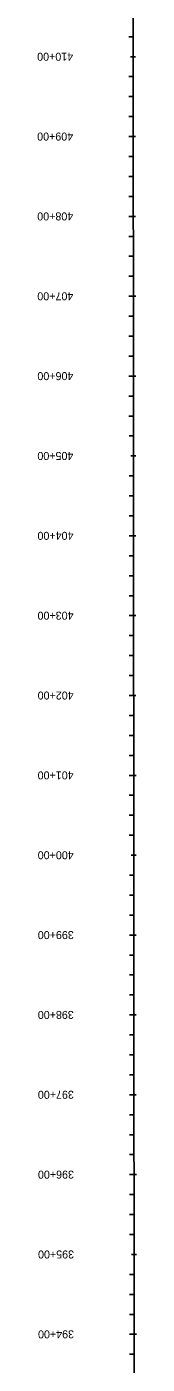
# Model space of a CAD drawing. Extents: x 23417911 to 23421158, y 6737892 to 6791804.
# Drawn here: x 23420714 to 23420838, y 6764860 to 6766535 of the extents above; entities that cross this region are included whole.
import ezdxf

# ---------------------------------------------------------------- set-up
doc = ezdxf.new("R2010")
doc.units = 0
for name, color, linetype in [('Alignment', 7, 'Continuous'), ('TextAlignmentLrg', 7, 'Continuous'), ('TextAlignmentSml', 7, 'Continuous')]:
    doc.layers.add(name, color=color, linetype=linetype)

msp = doc.modelspace()

# ---------------------------------------------------------------- linework, layer by layer
at = {"layer": 'Alignment'}
msp.add_line((23420834.6, 6764732), (23420829.5, 6771769.1), dxfattribs=at)
msp.add_line((23420834.6, 6764732), (23420829.5, 6771769.1), dxfattribs=at)
at = {"layer": 'TextAlignmentLrg'}
for p, q in [((23420830.2, 6766497.6), (23420836.3, 6766497.6)), ((23420833.4, 6766397.6), (23420827.9, 6766397.6)), ((23420833.4, 6766297.6), (23420828, 6766297.6)), ((23420833.5, 6766197.6), (23420828, 6766197.6)), ((23420833.6, 6766097.6), (23420828.1, 6766097.6)), ((23420830.6, 6765997.6), (23420836.7, 6765997.6)), ((23420833.7, 6765897.6), (23420828.3, 6765897.6)), ((23420833.8, 6765797.6), (23420828.3, 6765797.6)), ((23420833.9, 6765697.6), (23420828.4, 6765697.6)), ((23420833.9, 6765597.6), (23420828.5, 6765597.6)), ((23420830.9, 6765497.6), (23420837.1, 6765497.6)), ((23420834.1, 6765397.6), (23420828.6, 6765397.6)), ((23420834.2, 6765297.6), (23420828.7, 6765297.6)), ((23420834.2, 6765197.6), (23420828.8, 6765197.6)), ((23420834.3, 6765097.6), (23420828.8, 6765097.6)), ((23420831.3, 6764997.6), (23420837.4, 6764997.6)), ((23420834.4, 6764897.6), (23420829, 6764897.6))]:
    msp.add_line(p, q, dxfattribs=at)
at = {"layer": 'TextAlignmentSml'}
for p, q in [((23420833.3, 6766522.6), (23420827.8, 6766522.6)), ((23420830.2, 6766497.6), (23420836.3, 6766497.6)), ((23420833.3, 6766472.6), (23420827.8, 6766472.6)), ((23420833.3, 6766447.6), (23420827.9, 6766447.6)), ((23420833.3, 6766422.6), (23420827.9, 6766422.6)), ((23420830.3, 6766397.6), (23420836.4, 6766397.6)), ((23420833.4, 6766372.6), (23420827.9, 6766372.6)), ((23420833.4, 6766347.6), (23420827.9, 6766347.6)), ((23420833.4, 6766322.6), (23420827.9, 6766322.6)), ((23420830.4, 6766297.6), (23420836.5, 6766297.6)), ((23420833.4, 6766272.6), (23420828, 6766272.6)), ((23420833.5, 6766247.6), (23420828, 6766247.6)), ((23420833.5, 6766222.6), (23420828, 6766222.6)), ((23420830.4, 6766197.6), (23420836.6, 6766197.6)), ((23420833.5, 6766172.6), (23420828.1, 6766172.6)), ((23420833.5, 6766147.6), (23420828.1, 6766147.6)), ((23420833.6, 6766122.6), (23420828.1, 6766122.6)), ((23420830.5, 6766097.6), (23420836.6, 6766097.6)), ((23420833.6, 6766072.6), (23420828.1, 6766072.6)), ((23420833.6, 6766047.6), (23420828.1, 6766047.6)), ((23420833.6, 6766022.6), (23420828.2, 6766022.6)), ((23420830.6, 6765997.6), (23420836.7, 6765997.6)), ((23420833.7, 6765972.6), (23420828.2, 6765972.6)), ((23420833.7, 6765947.6), (23420828.2, 6765947.6)), ((23420833.7, 6765922.6), (23420828.2, 6765922.6)), ((23420830.7, 6765897.6), (23420836.8, 6765897.6)), ((23420833.7, 6765872.6), (23420828.3, 6765872.6)), ((23420833.8, 6765847.6), (23420828.3, 6765847.6)), ((23420833.8, 6765822.6), (23420828.3, 6765822.6)), ((23420830.7, 6765797.6), (23420836.8, 6765797.6)), ((23420833.8, 6765772.6), (23420828.3, 6765772.6)), ((23420833.8, 6765747.6), (23420828.4, 6765747.6)), ((23420833.8, 6765722.6), (23420828.4, 6765722.6)), ((23420830.8, 6765697.6), (23420836.9, 6765697.6)), ((23420833.9, 6765672.6), (23420828.4, 6765672.6)), ((23420833.9, 6765647.6), (23420828.4, 6765647.6)), ((23420833.9, 6765622.6), (23420828.5, 6765622.6)), ((23420830.9, 6765597.6), (23420837, 6765597.6)), ((23420834, 6765572.6), (23420828.5, 6765572.6)), ((23420834, 6765547.6), (23420828.5, 6765547.6)), ((23420834, 6765522.6), (23420828.5, 6765522.6)), ((23420830.9, 6765497.6), (23420837.1, 6765497.6)), ((23420834, 6765472.6), (23420828.6, 6765472.6)), ((23420834, 6765447.6), (23420828.6, 6765447.6)), ((23420834.1, 6765422.6), (23420828.6, 6765422.6)), ((23420831, 6765397.6), (23420837.1, 6765397.6)), ((23420834.1, 6765372.6), (23420828.6, 6765372.6)), ((23420834.1, 6765347.6), (23420828.7, 6765347.6)), ((23420834.1, 6765322.6), (23420828.7, 6765322.6)), ((23420831.1, 6765297.6), (23420837.2, 6765297.6)), ((23420834.2, 6765272.6), (23420828.7, 6765272.6)), ((23420834.2, 6765247.6), (23420828.7, 6765247.6)), ((23420834.2, 6765222.6), (23420828.7, 6765222.6)), ((23420831.2, 6765197.6), (23420837.3, 6765197.6)), ((23420834.2, 6765172.6), (23420828.8, 6765172.6)), ((23420834.3, 6765147.6), (23420828.8, 6765147.6)), ((23420834.3, 6765122.6), (23420828.8, 6765122.6)), ((23420831.2, 6765097.6), (23420837.4, 6765097.6)), ((23420834.3, 6765072.6), (23420828.9, 6765072.6)), ((23420834.3, 6765047.6), (23420828.9, 6765047.6)), ((23420834.3, 6765022.6), (23420828.9, 6765022.6)), ((23420831.3, 6764997.6), (23420837.4, 6764997.6)), ((23420834.4, 6764972.6), (23420828.9, 6764972.6)), ((23420834.4, 6764947.6), (23420828.9, 6764947.6)), ((23420834.4, 6764922.6), (23420829, 6764922.6)), ((23420831.4, 6764897.6), (23420837.5, 6764897.6)), ((23420834.5, 6764872.6), (23420829, 6764872.6))]:
    msp.add_line(p, q, dxfattribs=at)

# ---------------------------------------------------------------- texts
at = {"layer": 'TextAlignmentLrg'}
for s, p in [('410+00', (23420758.3, 6766502.6)), ('405+00', (23420758.6, 6766002.6)), ('400+00', (23420759, 6765502.6)), ('395+00', (23420759.4, 6765002.6))]:
    msp.add_text(s, height=10.02, rotation=180.0416, dxfattribs=at).set_placement(p)
at = {"layer": 'TextAlignmentSml'}
for s, p in [('410+00', (23420758.3, 6766502.6)), ('409+00', (23420758.3, 6766402.6)), ('408+00', (23420758.4, 6766302.6)), ('407+00', (23420758.5, 6766202.6)), ('406+00', (23420758.6, 6766102.6)), ('405+00', (23420758.6, 6766002.6)), ('404+00', (23420758.7, 6765902.6)), ('403+00', (23420758.8, 6765802.6)), ('402+00', (23420758.9, 6765702.6)), ('401+00', (23420758.9, 6765602.6)), ('400+00', (23420759, 6765502.6)), ('399+00', (23420759.1, 6765402.6)), ('398+00', (23420759.1, 6765302.6)), ('397+00', (23420759.2, 6765202.6)), ('396+00', (23420759.3, 6765102.6)), ('395+00', (23420759.4, 6765002.6)), ('394+00', (23420759.4, 6764902.6))]:
    msp.add_text(s, height=10.02, rotation=180.0416, dxfattribs=at).set_placement(p)

doc.saveas('drawing.dxf')
